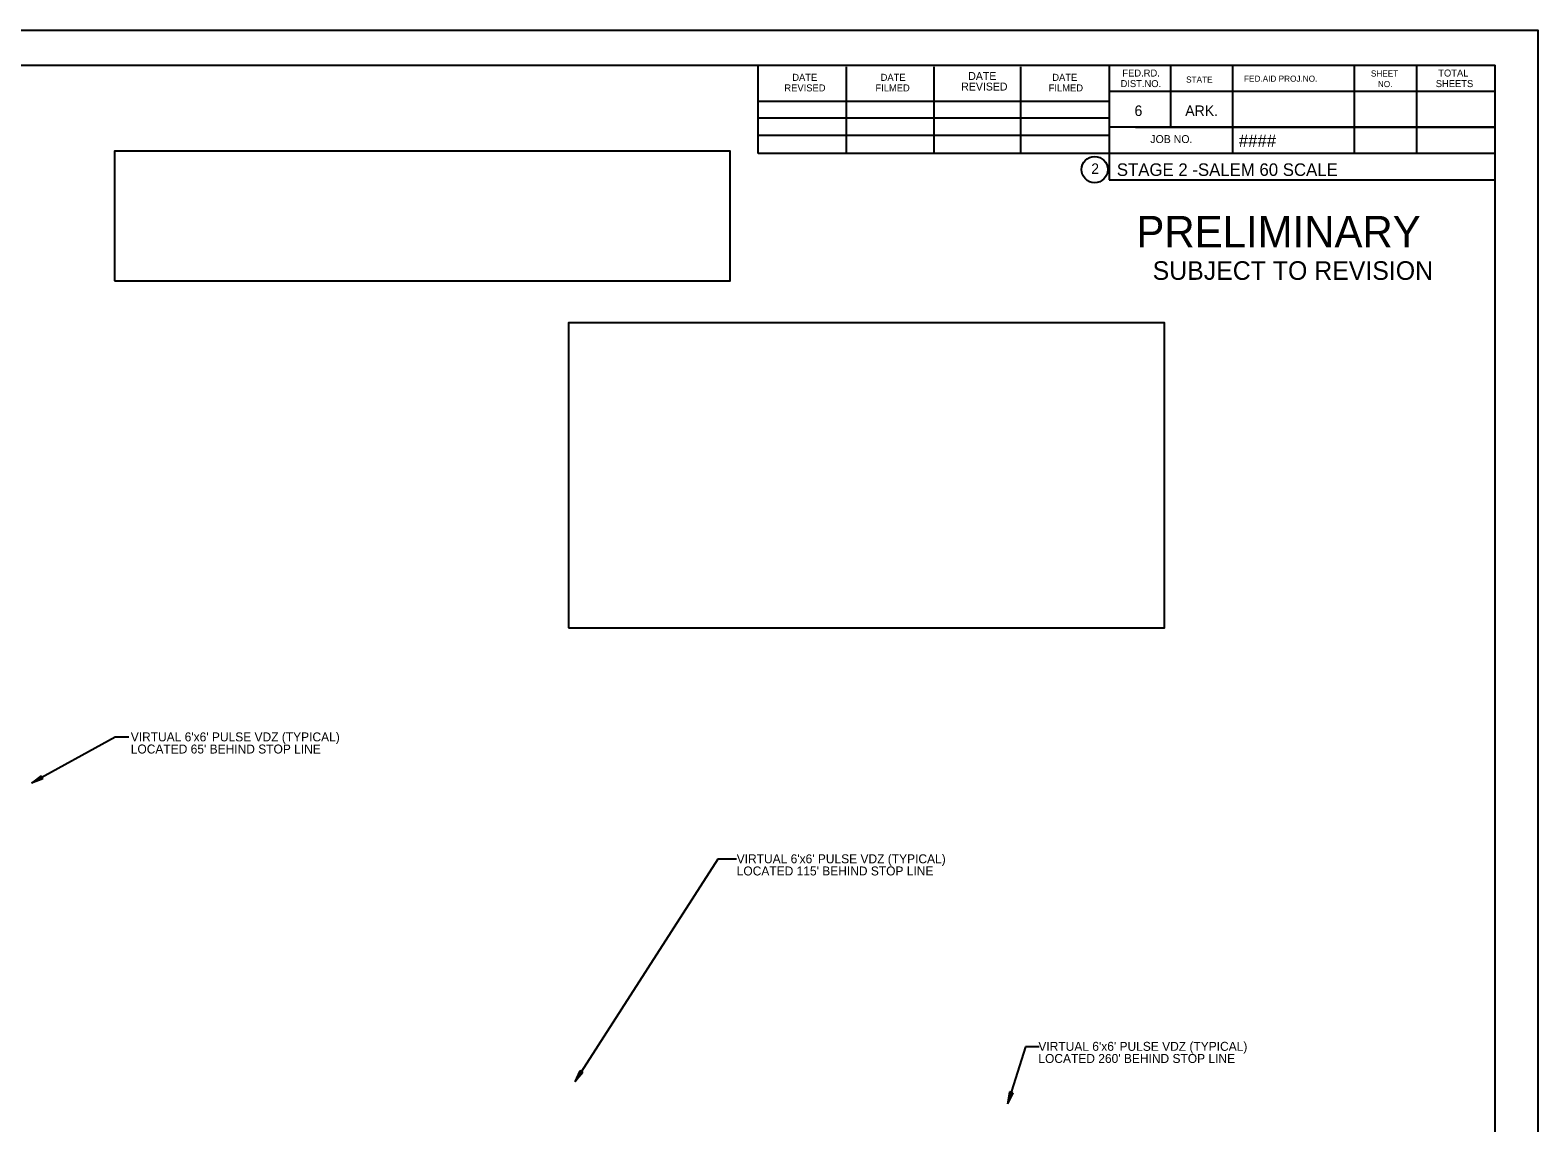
# Model space of a CAD drawing. Extents: x 659404 to 660404, y 642315 to 642955.
# Drawn here: x 659899 to 660404, y 642589 to 642955 of the extents above; entities that cross this region are included whole.
import ezdxf

# ---------------------------------------------------------------- set-up
doc = ezdxf.new("R2010")
doc.units = 0
for name, color, linetype in [('Default', 7, 'Continuous'), ('R_Border', 7, 'Continuous'), ('R_Border Prem', 7, 'Continuous'), ('R_No Plot', 7, 'Continuous'), ('T_Drafting', 7, 'Continuous')]:
    doc.layers.add(name, color=color, linetype=linetype)

msp = doc.modelspace()

# ---------------------------------------------------------------- linework, layer by layer
at = {"layer": 'Default'}
msp.add_lwpolyline([(660079.07, 642755.11), (660278.72, 642755.11), (660278.72, 642857.12), (660079.07, 642857.12)], close=True, dxfattribs=at)
at = {"layer": 'R_Border'}
for p, q in [((659440.89, 642943.46), (660389.43, 642943.46)), ((660142.65, 642913.82), (660142.65, 642943.46)), ((660172.23, 642913.82), (660172.23, 642942.86)), ((660201.51, 642913.82), (660201.51, 642942.86)), ((660230.55, 642913.82), (660230.55, 642942.86)), ((660260.13, 642943.46), (660260.13, 642905.06)), ((660280.65, 642943.46), (660280.65, 642922.64)), ((660301.47, 642943.46), (660301.47, 642913.82)), ((660342.21, 642943.46), (660342.21, 642913.82)), ((660363.03, 642943.46), (660363.03, 642913.82)), ((660389.43, 642327.08), (660389.43, 642943.46)), ((660142.65, 642931.4), (660260.13, 642931.4)), ((660389.43, 642934.64), (660260.13, 642934.64)), ((660389.43, 642934.7), (660389.43, 642934.7)), ((660142.65, 642925.82), (660260.13, 642925.82)), ((660142.65, 642913.82), (660142.65, 642920)), ((660142.65, 642920), (660260.13, 642920)), ((660389.43, 642922.64), (660260.13, 642922.64)), ((660269.01, 642922.64), (660389.43, 642922.64)), ((660389.43, 642913.82), (660142.65, 642913.82)), ((660260.13, 642905.06), (660389.43, 642905.06))]:
    msp.add_line(p, q, dxfattribs=at)
msp.add_circle((660255.29, 642908.47), 4.4, dxfattribs=at)
at = {"layer": 'R_No Plot'}
msp.add_line((659403.69, 642955.15), (660403.69, 642955.15), dxfattribs=at)
msp.add_lwpolyline([(659403.67, 642955.15), (660403.69, 642955.15), (660403.69, 642315.13), (659403.67, 642315.13)], close=True, dxfattribs=at)
at = {"layer": 'T_Drafting'}
for p, q in [((659927.32, 642718.44), (659899.29, 642703.08)), ((659931.91, 642718.44), (659927.32, 642718.44)), ((659902.51, 642705.52), (659899.29, 642703.08)), ((659903.09, 642704.47), (659899.29, 642703.08)), ((659902.56, 642705.44), (659899.88, 642703.4)), ((659903.04, 642704.56), (659899.88, 642703.4)), ((659902.61, 642705.35), (659900.48, 642703.73)), ((659902.99, 642704.65), (659900.48, 642703.73)), ((659902.66, 642705.26), (659901.07, 642704.05)), ((659902.94, 642704.74), (659901.07, 642704.05)), ((659902.71, 642705.17), (659901.66, 642704.37)), ((659902.89, 642704.83), (659901.66, 642704.37)), ((659902.75, 642705.08), (659902.25, 642704.69)), ((659902.84, 642704.92), (659902.25, 642704.69)), ((659903.09, 642704.47), (659902.51, 642705.52)), ((660129.14, 642677.62), (660081.29, 642603.12)), ((660135.36, 642677.62), (660129.14, 642677.62)), ((660232.11, 642614.79), (660226.11, 642595.76)), ((660236.7, 642614.79), (660232.11, 642614.79)), ((660082.95, 642606.81), (660081.29, 642603.12)), ((660083.03, 642606.75), (660081.65, 642603.68)), ((660083.96, 642606.16), (660082.95, 642606.81)), ((660083.96, 642606.16), (660081.29, 642603.12)), ((660083.87, 642606.21), (660081.65, 642603.68)), ((660083.12, 642606.7), (660082.02, 642604.26)), ((660083.79, 642606.27), (660082.02, 642604.26)), ((660083.2, 642606.64), (660082.38, 642604.82)), ((660083.7, 642606.32), (660082.38, 642604.82)), ((660083.29, 642606.59), (660082.75, 642605.39)), ((660083.62, 642606.38), (660082.75, 642605.39)), ((660083.37, 642606.53), (660083.11, 642605.95)), ((660083.53, 642606.43), (660083.11, 642605.95)), ((660226.74, 642599.76), (660226.11, 642595.76)), ((660227.88, 642599.4), (660226.11, 642595.76)), ((660226.83, 642599.73), (660226.31, 642596.4)), ((660227.79, 642599.43), (660226.31, 642596.4)), ((660226.93, 642599.7), (660226.51, 642597.06)), ((660227.69, 642599.46), (660226.51, 642597.06)), ((660227.02, 642599.67), (660226.71, 642597.69)), ((660227.59, 642599.49), (660226.71, 642597.69)), ((660227.88, 642599.4), (660226.74, 642599.76)), ((660227.12, 642599.64), (660226.92, 642598.34)), ((660227.49, 642599.52), (660226.92, 642598.34)), ((660227.22, 642599.61), (660227.12, 642598.98)), ((660227.4, 642599.55), (660227.12, 642598.98))]:
    msp.add_line(p, q, dxfattribs=at)
msp.add_lwpolyline([(659927.1, 642871.28), (660133.27, 642871.28), (660133.27, 642914.69), (659927.1, 642914.69)], close=True, dxfattribs=at)

# ---------------------------------------------------------------- texts
at = {"layer": 'R_Border'}
for s, height, p in [('DATE', 2.346, (660154.05, 642938.18)), ('DATE', 2.346, (660183.63, 642938.18)), ('DATE', 2.638, (660212.97, 642938.48)), ('DATE', 2.346, (660241.11, 642938.18)), ('FED.RD.', 2.346, (660264.57, 642939.62)), ('FED.AID PROJ.NO.', 2.052, (660305.31, 642937.88)), ('SHEET', 2.052, (660347.79, 642939.62)), ('TOTAL', 2.346, (660370.35, 642939.62)), ('REVISED', 2.346, (660151.41, 642934.64)), ('FILMED', 2.346, (660181.89, 642934.64)), ('REVISED', 2.638, (660210.63, 642934.94)), ('FILMED', 2.346, (660239.91, 642934.64)), ('DIST.NO.', 2.346, (660263.97, 642936.08)), ('STATE', 2.052, (660285.93, 642937.58)), ('NO.', 2.052, (660350.13, 642936.08)), ('SHEETS', 2.346, (660369.51, 642936.08)), ('6', 3.52, (660268.65, 642926.42)), ('ARK.', 3.517, (660285.63, 642926.42)), ('JOB NO.', 2.638, (660273.93, 642917.36)), ('####', 4.2, (660303.56, 642916.04)), ('2', 3.52, (660254.14, 642907.01)), ('STAGE 2 -SALEM 60 SCALE', 4.2, (660262.72, 642906.35))]:
    msp.add_text(s, height=height, rotation=360, dxfattribs=at).set_placement(p)
at = {"layer": 'R_Border Prem'}
for s, height, p in [('PRELIMINARY', 10.5, (660269.28, 642882.45)), ('SUBJECT TO REVISION', 6.2253, (660274.71, 642871.56))]:
    msp.add_text(s, height=height, rotation=360, dxfattribs=at).set_placement(p)
at = {"layer": 'T_Drafting'}
for s, p in [("VIRTUAL 6'x6' PULSE VDZ (TYPICAL)", (659932.56, 642717.06)), ("LOCATED 65' BEHIND STOP LINE", (659932.56, 642713)), ("VIRTUAL 6'x6' PULSE VDZ (TYPICAL)", (660135.45, 642676.25)), ("LOCATED 115' BEHIND STOP LINE", (660135.45, 642672.18)), ("VIRTUAL 6'x6' PULSE VDZ (TYPICAL)", (660236.45, 642613.47)), ("LOCATED 260' BEHIND STOP LINE", (660236.45, 642609.41))]:
    msp.add_text(s, height=3, dxfattribs=at).set_placement(p)

doc.saveas('drawing.dxf')
